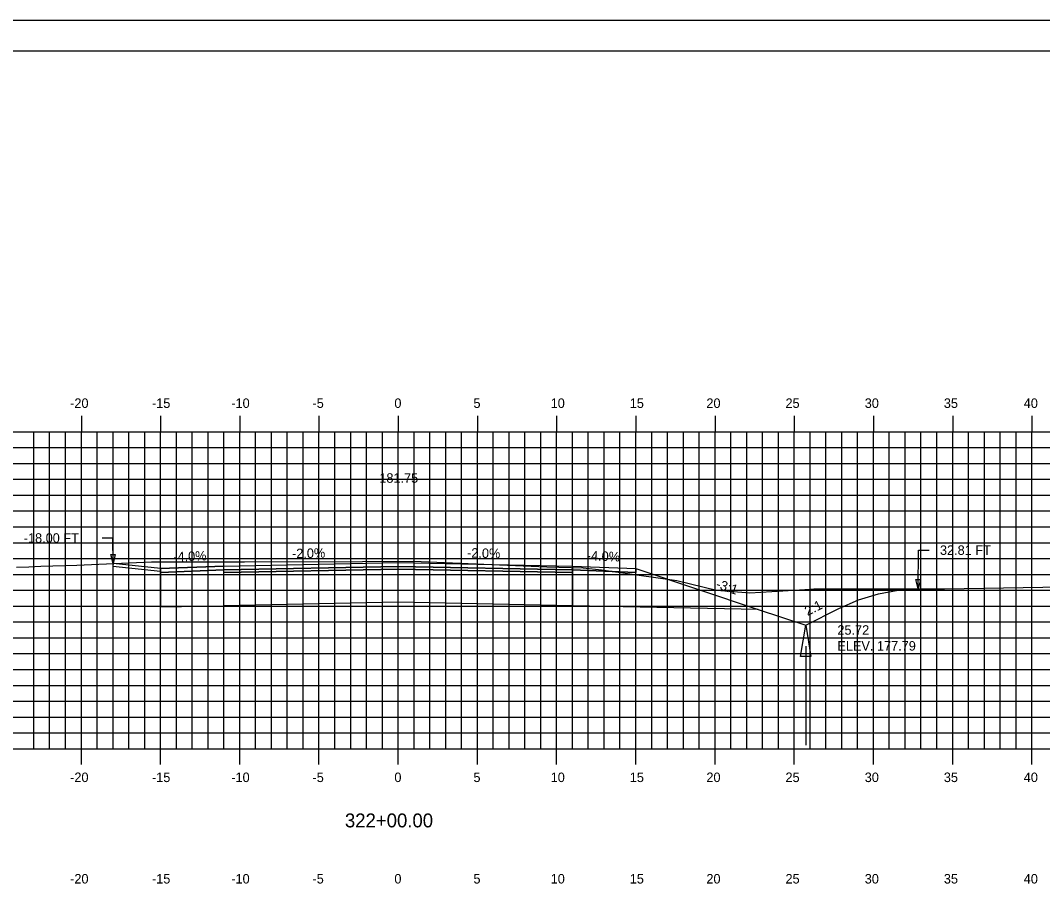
# Model space of a CAD drawing. Extents: x 1139872 to 1140042, y 608981 to 609091.
# Drawn here: x 1139931.1 to 1139995.6, y 609036.6 to 609091.3 of the extents above; entities that cross this region are included whole.
import ezdxf

# ---------------------------------------------------------------- set-up
doc = ezdxf.new("R2010")
doc.units = 0
for name, color, linetype in [('ANNOTATION', 7, 'Continuous'), ('BORDER', 7, 'Continuous'), ('D_Drainage_Ditch_Line', 7, 'Continuous'), ('D_Roadway_Centerline', 7, 'Continuous'), ('D_Roadway_Centerline_Text', 7, 'Continuous'), ('D_Roadway_Edge_Shoulder', 7, 'Continuous'), ('D_Roadway_Edge_TW', 7, 'Continuous'), ('D_Roadway_Pavement', 7, 'Continuous'), ('D_Roadway_SlopeLines', 7, 'Continuous'), ('D_Roadway_SubGrade', 7, 'Continuous'), ('D_Text_Standard', 7, 'Continuous'), ('H_V ANNOTATION', 7, 'Continuous'), ('MAJOR', 7, 'Continuous'), ('MINOR', 7, 'Continuous'), ('PLOT BOUNDARY', 7, 'Continuous'), ('S_Roadway_Centerline', 7, 'Continuous')]:
    doc.layers.add(name, color=color, linetype=linetype)

msp = doc.modelspace()

# ---------------------------------------------------------------- linework, layer by layer
msp.add_lwpolyline([(1139939.974, 609056.702), (1139939.975, 609056.702), (1139943.975, 609056.862), (1139954.975, 609057.082), (1139965.975, 609056.862), (1139969.975, 609056.702), (1139977.698, 609054.128), (1139980.698, 609053.128), (1139982.789, 609054.173), (1139984.039, 609054.72), (1139985.289, 609055.111), (1139986.539, 609055.347), (1139987.789, 609055.426)])
at = {"layer": 'BORDER'}
msp.add_lwpolyline([(1139879.975, 608984.335), (1140039.975, 608984.335), (1140039.975, 609089.335), (1139879.975, 609089.335)], close=True, dxfattribs=at)
at = {"layer": 'D_Drainage_Ditch_Line'}
msp.add_line((1139980.698, 609051.816), (1139980.698, 609045.572), dxfattribs=at)
msp.add_lwpolyline([(1139981.026, 609051.159), (1139980.37, 609051.159), (1139980.698, 609053.128)], close=True, dxfattribs=at)
at = {"layer": 'D_Roadway_Edge_Shoulder'}
for points in [[(1139939.975, 609056.702), (1139936.975, 609057.013), (1139936.958, 609056.847), (1139939.975, 609056.535)], [(1139943.975, 609056.862), (1139939.975, 609056.702), (1139939.975, 609056.452), (1139943.975, 609056.612)], [(1139965.975, 609056.862), (1139969.975, 609056.702), (1139969.975, 609056.452), (1139965.975, 609056.612)]]:
    msp.add_lwpolyline(points, close=True, dxfattribs=at)
at = {"layer": 'D_Roadway_Edge_TW'}
msp.add_lwpolyline([(1139943.975, 609056.612), (1139943.975, 609056.862), (1139954.975, 609057.082), (1139965.975, 609056.862), (1139965.975, 609056.612), (1139954.975, 609056.832)], close=True, dxfattribs=at)
at = {"layer": 'D_Roadway_Pavement'}
msp.add_lwpolyline([(1139943.975, 609056.446), (1139943.975, 609056.612), (1139954.975, 609056.832), (1139965.975, 609056.612), (1139965.975, 609056.446), (1139954.975, 609056.666)], close=True, dxfattribs=at)
at = {"layer": 'D_Roadway_SlopeLines'}
for points in [[(1139980.698, 609053.128), (1139982.789, 609054.173), (1139984.039, 609054.72), (1139985.289, 609055.111), (1139986.539, 609055.347), (1139987.789, 609055.426)], [(1139977.698, 609054.128), (1139980.698, 609053.128)]]:
    msp.add_lwpolyline(points, dxfattribs=at)
at = {"layer": 'D_Roadway_SubGrade'}
for points in [[(1139939.974, 609055.702), (1139939.975, 609054.282), (1139943.975, 609054.362), (1139943.975, 609056.446), (1139943.975, 609056.612), (1139939.975, 609056.452), (1139939.975, 609056.702), (1139939.974, 609056.702)], [(1139943.975, 609054.362), (1139943.975, 609056.446), (1139954.975, 609056.666), (1139965.975, 609056.446), (1139965.975, 609054.362), (1139954.975, 609054.582)], [(1139965.975, 609056.446), (1139965.975, 609056.612), (1139969.975, 609056.452), (1139969.975, 609056.702), (1139969.975, 609056.702), (1139977.698, 609054.128), (1139965.975, 609054.362)]]:
    msp.add_lwpolyline(points, close=True, dxfattribs=at)
at = {"layer": 'D_Text_Standard'}
for points in [[(1139936.975, 609057.013), (1139936.971, 609058.63), (1139936.291, 609058.63)], [(1139987.789, 609055.423), (1139987.813, 609057.864), (1139988.493, 609057.864)]]:
    msp.add_lwpolyline(points, dxfattribs=at)
for points in [[(1139936.975, 609057.013), (1139936.828, 609057.594), (1139937.119, 609057.595)], [(1139987.789, 609055.423), (1139987.649, 609056.007), (1139987.94, 609056.004)]]:
    msp.add_lwpolyline(points, close=True, dxfattribs=at)
at = {"layer": 'MAJOR'}
for p, q in [((1139934.975, 609066.337), (1139934.975, 609065.335)), ((1139939.975, 609066.337), (1139939.975, 609065.335)), ((1139944.975, 609066.337), (1139944.975, 609065.335)), ((1139949.975, 609066.337), (1139949.975, 609065.335)), ((1139954.975, 609066.337), (1139954.975, 609065.335)), ((1139959.975, 609066.337), (1139959.975, 609065.335)), ((1139964.975, 609066.337), (1139964.975, 609065.335)), ((1139969.975, 609066.337), (1139969.975, 609065.335)), ((1139974.975, 609066.337), (1139974.975, 609065.335)), ((1139979.975, 609066.337), (1139979.975, 609065.335)), ((1139984.975, 609066.337), (1139984.975, 609065.335)), ((1139989.975, 609066.337), (1139989.975, 609065.335)), ((1139994.975, 609066.337), (1139994.975, 609065.335)), ((1139884.975, 609065.335), (1140024.975, 609065.335)), ((1139884.975, 609065.335), (1140024.975, 609065.335)), ((1139934.975, 609045.335), (1139934.975, 609065.335)), ((1139939.975, 609045.335), (1139939.975, 609065.335)), ((1139944.975, 609045.335), (1139944.975, 609065.335)), ((1139949.975, 609045.335), (1139949.975, 609065.335)), ((1139954.975, 609045.335), (1139954.975, 609065.335)), ((1139959.975, 609045.335), (1139959.975, 609065.335)), ((1139964.975, 609045.335), (1139964.975, 609065.335)), ((1139969.975, 609045.335), (1139969.975, 609065.335)), ((1139974.975, 609045.335), (1139974.975, 609065.335)), ((1139979.975, 609045.335), (1139979.975, 609065.335)), ((1139984.975, 609045.335), (1139984.975, 609065.335)), ((1139989.975, 609045.335), (1139989.975, 609065.335)), ((1139994.975, 609045.335), (1139994.975, 609065.335)), ((1139884.975, 609060.335), (1140024.975, 609060.335)), ((1139884.975, 609055.335), (1140024.975, 609055.335)), ((1139884.975, 609050.335), (1140024.975, 609050.335)), ((1139884.975, 609045.335), (1140024.975, 609045.335)), ((1139884.975, 609045.335), (1140024.975, 609045.335)), ((1139934.975, 609044.333), (1139934.975, 609045.335)), ((1139939.975, 609044.333), (1139939.975, 609045.335)), ((1139944.975, 609044.333), (1139944.975, 609045.335)), ((1139949.975, 609044.333), (1139949.975, 609045.335)), ((1139954.975, 609044.333), (1139954.975, 609045.335)), ((1139959.975, 609044.333), (1139959.975, 609045.335)), ((1139964.975, 609044.333), (1139964.975, 609045.335)), ((1139969.975, 609044.333), (1139969.975, 609045.335)), ((1139974.975, 609044.333), (1139974.975, 609045.335)), ((1139979.975, 609044.333), (1139979.975, 609045.335)), ((1139984.975, 609044.333), (1139984.975, 609045.335)), ((1139989.975, 609044.333), (1139989.975, 609045.335)), ((1139994.975, 609044.333), (1139994.975, 609045.335))]:
    msp.add_line(p, q, dxfattribs=at)
at = {"layer": 'MINOR'}
for p, q in [((1139931.975, 609045.335), (1139931.975, 609065.335)), ((1139932.975, 609045.335), (1139932.975, 609065.335)), ((1139933.975, 609045.335), (1139933.975, 609065.335)), ((1139935.975, 609045.335), (1139935.975, 609065.335)), ((1139936.975, 609045.335), (1139936.975, 609065.335)), ((1139937.975, 609045.335), (1139937.975, 609065.335)), ((1139938.975, 609045.335), (1139938.975, 609065.335)), ((1139940.975, 609045.335), (1139940.975, 609065.335)), ((1139941.975, 609045.335), (1139941.975, 609065.335)), ((1139942.975, 609045.335), (1139942.975, 609065.335)), ((1139943.975, 609045.335), (1139943.975, 609065.335)), ((1139945.975, 609045.335), (1139945.975, 609065.335)), ((1139946.975, 609045.335), (1139946.975, 609065.335)), ((1139947.975, 609045.335), (1139947.975, 609065.335)), ((1139948.975, 609045.335), (1139948.975, 609065.335)), ((1139950.975, 609045.335), (1139950.975, 609065.335)), ((1139951.975, 609045.335), (1139951.975, 609065.335)), ((1139952.975, 609045.335), (1139952.975, 609065.335)), ((1139953.975, 609045.335), (1139953.975, 609065.335)), ((1139955.975, 609045.335), (1139955.975, 609065.335)), ((1139956.975, 609045.335), (1139956.975, 609065.335)), ((1139957.975, 609045.335), (1139957.975, 609065.335)), ((1139958.975, 609045.335), (1139958.975, 609065.335)), ((1139960.975, 609045.335), (1139960.975, 609065.335)), ((1139961.975, 609045.335), (1139961.975, 609065.335)), ((1139962.975, 609045.335), (1139962.975, 609065.335)), ((1139963.975, 609045.335), (1139963.975, 609065.335)), ((1139965.975, 609045.335), (1139965.975, 609065.335)), ((1139966.975, 609045.335), (1139966.975, 609065.335)), ((1139967.975, 609045.335), (1139967.975, 609065.335)), ((1139968.975, 609045.335), (1139968.975, 609065.335)), ((1139970.975, 609045.335), (1139970.975, 609065.335)), ((1139971.975, 609045.335), (1139971.975, 609065.335)), ((1139972.975, 609045.335), (1139972.975, 609065.335)), ((1139973.975, 609045.335), (1139973.975, 609065.335)), ((1139975.975, 609045.335), (1139975.975, 609065.335)), ((1139976.975, 609045.335), (1139976.975, 609065.335)), ((1139977.975, 609045.335), (1139977.975, 609065.335)), ((1139978.975, 609045.335), (1139978.975, 609065.335)), ((1139980.975, 609045.335), (1139980.975, 609065.335)), ((1139981.975, 609045.335), (1139981.975, 609065.335)), ((1139982.975, 609045.335), (1139982.975, 609065.335)), ((1139983.975, 609045.335), (1139983.975, 609065.335)), ((1139985.975, 609045.335), (1139985.975, 609065.335)), ((1139986.975, 609045.335), (1139986.975, 609065.335)), ((1139987.975, 609045.335), (1139987.975, 609065.335)), ((1139988.975, 609045.335), (1139988.975, 609065.335)), ((1139990.975, 609045.335), (1139990.975, 609065.335)), ((1139991.975, 609045.335), (1139991.975, 609065.335)), ((1139992.975, 609045.335), (1139992.975, 609065.335)), ((1139993.975, 609045.335), (1139993.975, 609065.335)), ((1139884.975, 609064.335), (1140024.975, 609064.335)), ((1139884.975, 609063.335), (1140024.975, 609063.335)), ((1139884.975, 609062.335), (1140024.975, 609062.335)), ((1139884.975, 609061.335), (1140024.975, 609061.335)), ((1139884.975, 609059.335), (1140024.975, 609059.335)), ((1139884.975, 609058.335), (1140024.975, 609058.335)), ((1139884.975, 609057.335), (1140024.975, 609057.335)), ((1139884.975, 609056.335), (1140024.975, 609056.335)), ((1139884.975, 609054.335), (1140024.975, 609054.335)), ((1139884.975, 609053.335), (1140024.975, 609053.335)), ((1139884.975, 609052.335), (1140024.975, 609052.335)), ((1139884.975, 609051.335), (1140024.975, 609051.335)), ((1139884.975, 609049.335), (1140024.975, 609049.335)), ((1139884.975, 609048.335), (1140024.975, 609048.335)), ((1139884.975, 609047.335), (1140024.975, 609047.335)), ((1139884.975, 609046.335), (1140024.975, 609046.335))]:
    msp.add_line(p, q, dxfattribs=at)
at = {"layer": 'PLOT BOUNDARY'}
msp.add_lwpolyline([(1139871.882, 608981.276), (1140041.882, 608981.276), (1140041.882, 609091.276), (1139871.882, 609091.276)], close=True, dxfattribs=at)
at = {"layer": 'S_Roadway_Centerline'}
msp.add_lwpolyline([(1139930.884, 609056.791), (1139931.658, 609056.822), (1139932.426, 609056.847), (1139934.697, 609056.914), (1139936.076, 609056.974), (1139939.396, 609057.117), (1139943.942, 609057.129), (1139944.356, 609057.129), (1139944.422, 609057.128), (1139944.902, 609057.132), (1139945.271, 609057.133), (1139952.732, 609057.149), (1139955.924, 609057.169), (1139964.361, 609056.81), (1139966.646, 609056.743), (1139967.807, 609056.618), (1139971.679, 609056.085), (1139972.111, 609056.019), (1139972.556, 609055.943), (1139975.061, 609055.348), (1139976.673, 609055.213), (1139977.181, 609055.182), (1139980.642, 609055.386), (1139981.206, 609055.419), (1139989.449, 609055.428), (1139998.159, 609055.571)], dxfattribs=at)

# ---------------------------------------------------------------- texts
at = {"layer": 'ANNOTATION'}
for s, rotation, p in [('-4.0%', 2.29061, (1139940.791, 609057.136)), ('-2.0%', 1.14576, (1139948.278, 609057.349)), ('-2.0%', 358.85424, (1139959.318, 609057.396)), ('-4.0%', 357.70939, (1139966.871, 609057.227)), ('-3:1', 341.56521, (1139974.986, 609055.486)), ('2:1', 26.56505, (1139980.816, 609053.705))]:
    msp.add_text(s, height=0.6, rotation=rotation, dxfattribs=at).set_placement(p)
at = {"layer": 'D_Roadway_Centerline'}
for s, p in [('C', (1139954.97, 609057.082)), ('L', (1139954.975, 609057.075))]:
    msp.add_text(s, height=0.0146, dxfattribs=at).set_placement(p)
at = {"layer": 'D_Roadway_Centerline_Text'}
msp.add_text('181.75', height=0.6, dxfattribs=at).set_placement((1139953.784, 609062.114))
at = {"layer": 'D_Text_Standard'}
for s, p in [('-18.00 FT', (1139931.34, 609058.33)), ('32.81 FT', (1139989.173, 609057.564)), ('25.72', (1139982.698, 609052.528)), ('ELEV. 177.79', (1139982.698, 609051.526))]:
    msp.add_text(s, height=0.6, dxfattribs=at).set_placement(p)
at = {"layer": 'H_V ANNOTATION'}
for s, height, p in [('-20', 0.6, (1139934.268, 609066.835)), ('-15', 0.6, (1139939.432, 609066.835)), ('-10', 0.6, (1139944.44, 609066.835)), ('-5', 0.6, (1139949.565, 609066.835)), ('0', 0.6, (1139954.734, 609066.835)), ('5', 0.6, (1139959.726, 609066.835)), ('10', 0.6, (1139964.6, 609066.835)), ('15', 0.6, (1139969.592, 609066.835)), ('20', 0.6, (1139974.429, 609066.835)), ('25', 0.6, (1139979.421, 609066.835)), ('30', 0.6, (1139984.424, 609066.835)), ('35', 0.6, (1139989.416, 609066.835)), ('40', 0.6, (1139994.461, 609066.835)), ('-20', 0.6, (1139934.268, 609043.235)), ('-15', 0.6, (1139939.432, 609043.235)), ('-10', 0.6, (1139944.44, 609043.235)), ('-5', 0.6, (1139949.565, 609043.235)), ('0', 0.6, (1139954.734, 609043.235)), ('5', 0.6, (1139959.726, 609043.235)), ('10', 0.6, (1139964.6, 609043.235)), ('15', 0.6, (1139969.592, 609043.235)), ('20', 0.6, (1139974.429, 609043.235)), ('25', 0.6, (1139979.421, 609043.235)), ('30', 0.6, (1139984.424, 609043.235)), ('35', 0.6, (1139989.416, 609043.235)), ('40', 0.6, (1139994.461, 609043.235)), ('322+00.00', 0.875, (1139951.612, 609040.378)), ('-20', 0.6, (1139934.268, 609036.835)), ('-15', 0.6, (1139939.432, 609036.835)), ('-10', 0.6, (1139944.44, 609036.835)), ('-5', 0.6, (1139949.565, 609036.835)), ('0', 0.6, (1139954.734, 609036.835)), ('5', 0.6, (1139959.726, 609036.835)), ('10', 0.6, (1139964.6, 609036.835)), ('15', 0.6, (1139969.592, 609036.835)), ('20', 0.6, (1139974.429, 609036.835)), ('25', 0.6, (1139979.421, 609036.835)), ('30', 0.6, (1139984.424, 609036.835)), ('35', 0.6, (1139989.416, 609036.835)), ('40', 0.6, (1139994.461, 609036.835))]:
    msp.add_text(s, height=height, dxfattribs=at).set_placement(p)
at = {"layer": 'S_Roadway_Centerline'}
for s, p in [('C', (1139955.919, 609057.169)), ('L', (1139955.924, 609057.162))]:
    msp.add_text(s, height=0.0146, dxfattribs=at).set_placement(p)

doc.saveas('drawing.dxf')
